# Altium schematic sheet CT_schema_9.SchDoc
size 387 x 278 mm
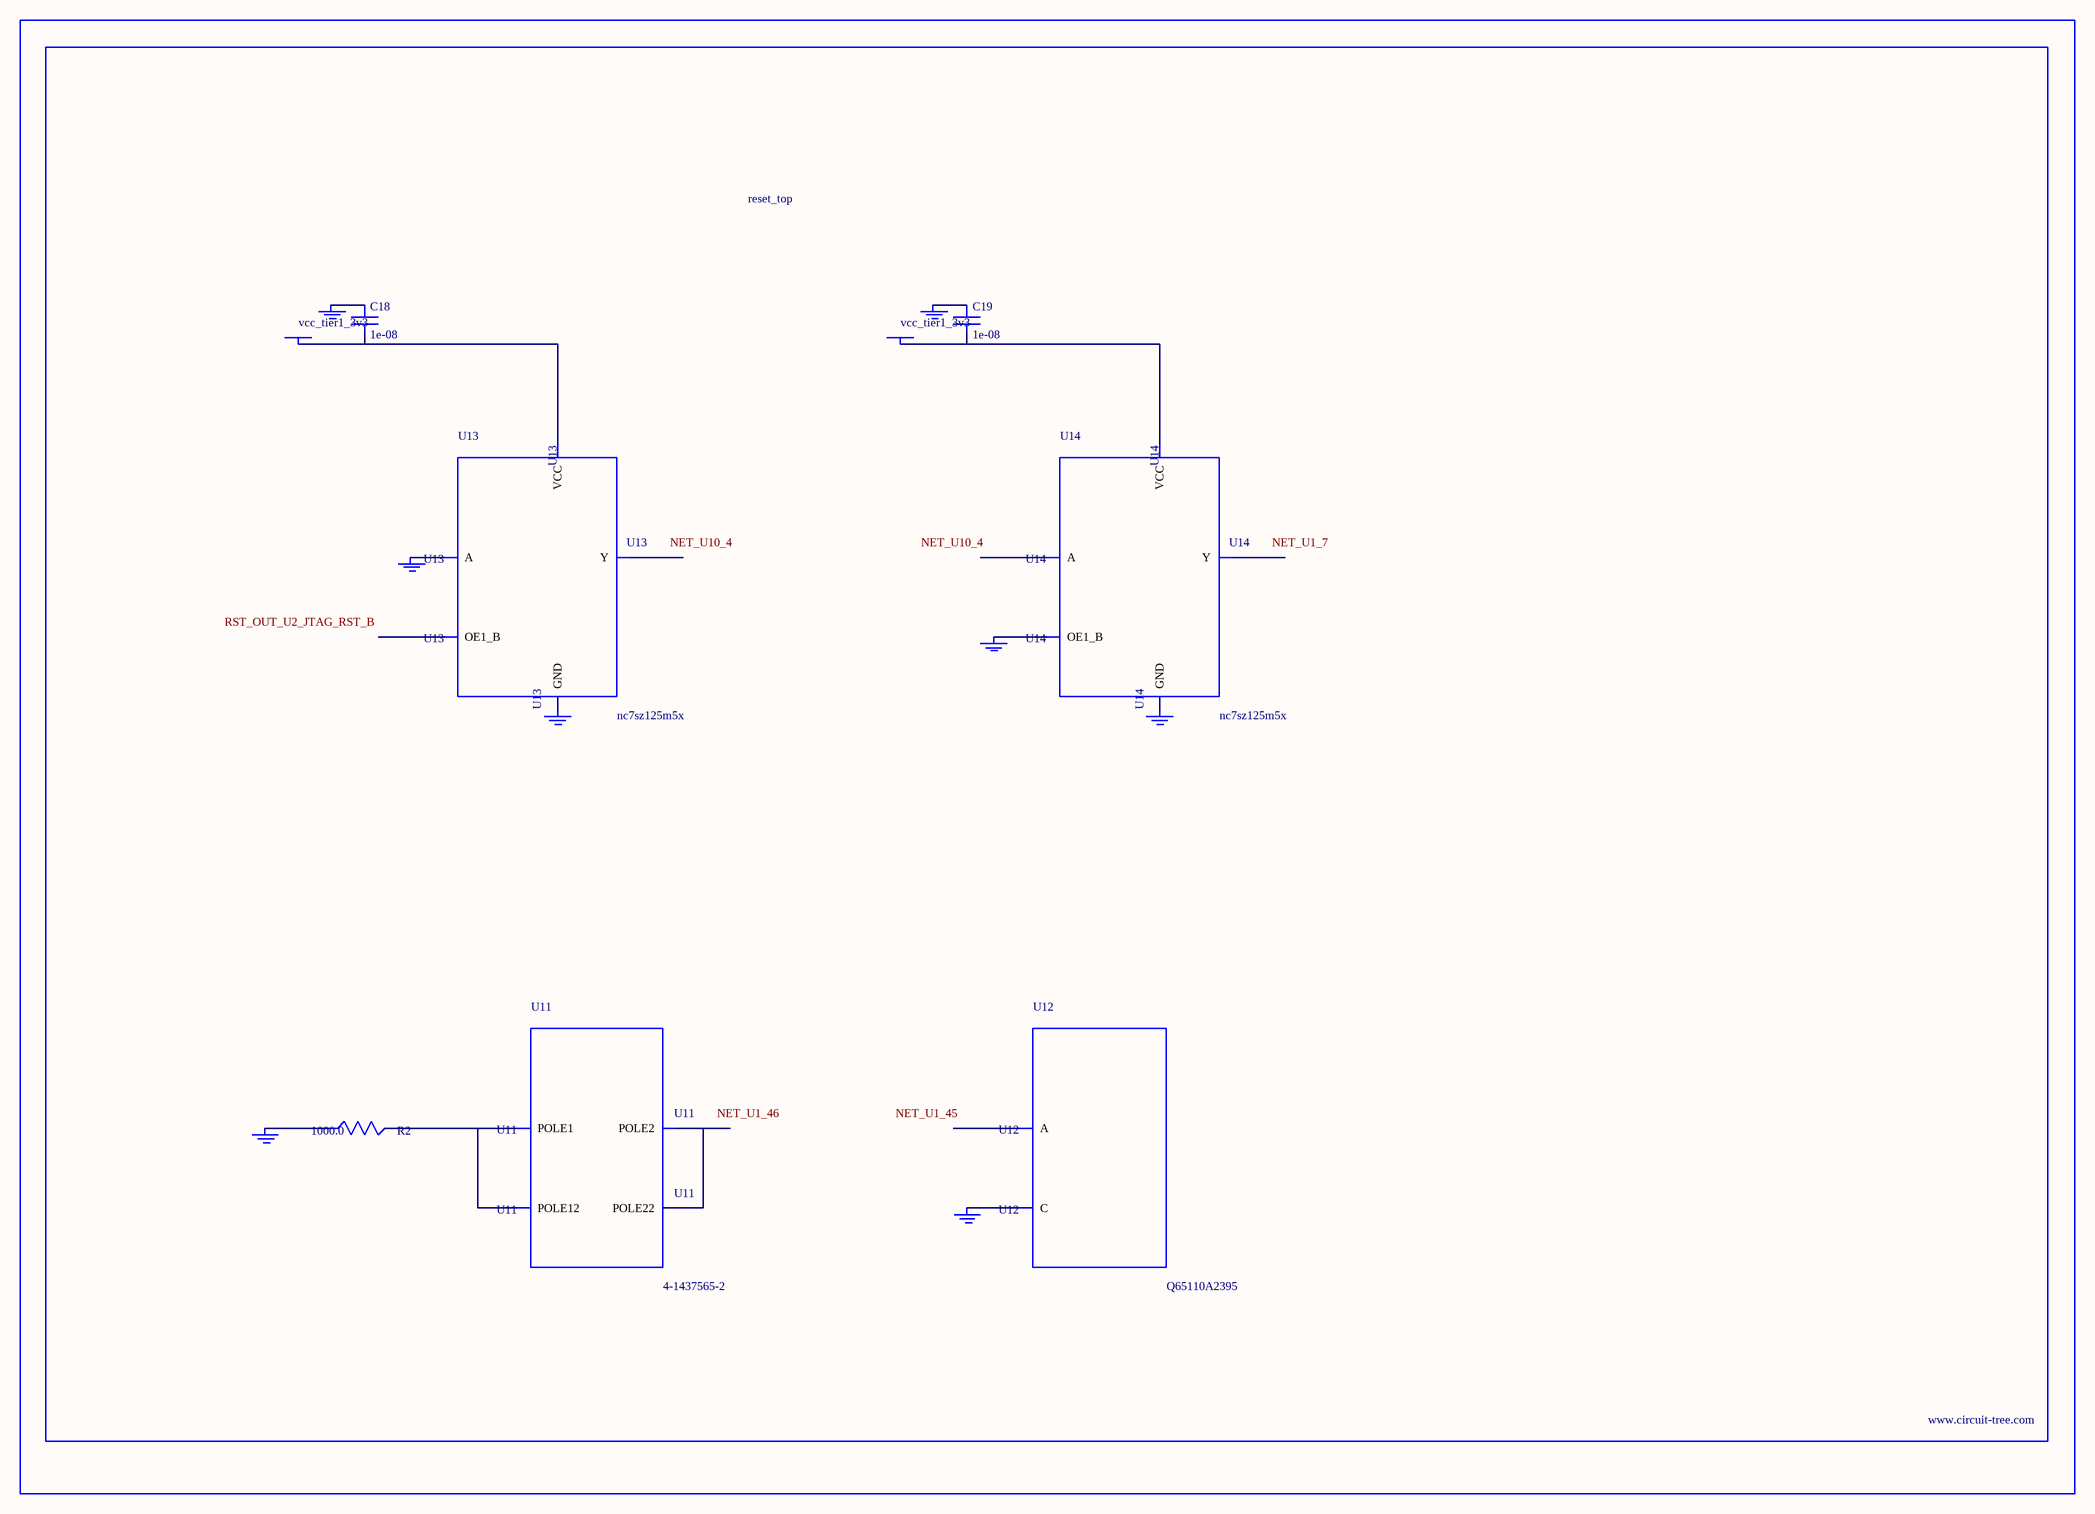
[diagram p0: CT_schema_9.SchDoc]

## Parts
BORDER8  (no value)
C18  1e-08  [C0402]
C19  1e-08  [C0402]
GND_INSTANCE_8_0  (no value)
GND_INSTANCE_8_1  (no value)
GND_INSTANCE_8_2  (no value)
GND_INSTANCE_8_3  (no value)
GND_INSTANCE_8_4  (no value)
GND_INSTANCE_8_5  (no value)
GND_INSTANCE_8_6  (no value)
GND_INSTANCE_8_7  (no value)
POWER_INSTANCE_8_0  vcc_tier1_3v3
POWER_INSTANCE_8_1  vcc_tier1_3v3
R2  1000.0  [R0603]
U11  4-1437565-2  [SW_4-1437565-2]
U12  Q65110A2395  [LGM67K-G1J2-24-Z]
U13  nc7sz125m5x  [NC7SZ125M5X]
U14  nc7sz125m5x  [NC7SZ125M5X]

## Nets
NetC18_1: C18.1 GND_INSTANCE_8_2.0(GND)
NetC18_2: C18.2 POWER_INSTANCE_8_0.0(PWR) U13.5(VCC)
NetC19_1: C19.1 GND_INSTANCE_8_5.0(GND)
NetC19_2: C19.2 POWER_INSTANCE_8_1.0(PWR) U14.5(VCC)
NetGND_INSTANCE_8_0_0: GND_INSTANCE_8_0.0(GND) R2.1
NetGND_INSTANCE_8_1_0: GND_INSTANCE_8_1.0(GND) U12.C
NetGND_INSTANCE_8_3_0: GND_INSTANCE_8_3.0(GND) U13.2(A)
NetGND_INSTANCE_8_4_0: GND_INSTANCE_8_4.0(GND) U13.3(GND)
NetGND_INSTANCE_8_6_0: GND_INSTANCE_8_6.0(GND) U14.1(OE1_B)
NetGND_INSTANCE_8_7_0: GND_INSTANCE_8_7.0(GND) U14.3(GND)
NetR2_2: R2.2 U11.1(POLE1) U11.2(POLE12)
NetU11_3: U11.3(POLE2) U11.4(POLE22)

Not connected (* = marked no-connect by the designer): U12 A; U13 1(OE1_B) 4(Y); U14 2(A) 4(Y)

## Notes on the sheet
- Labels drawn without touching a wire or pin: NET_U1_7, NET_U1_45, NET_U1_46, NET_U10_4, RST_OUT_U2_JTAG_RST_B

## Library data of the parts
BORDER8 = BORDER_PAGE8
C18 C19 = C0402C103K3RAC
GND_INSTANCE_8_0-GND_INSTANCE_8_7 = GND
POWER_INSTANCE_8_0 POWER_INSTANCE_8_1 = PWR
R2 = RC0603JR-071KL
